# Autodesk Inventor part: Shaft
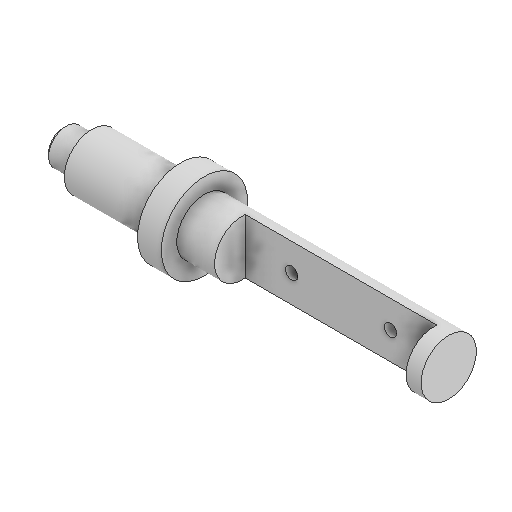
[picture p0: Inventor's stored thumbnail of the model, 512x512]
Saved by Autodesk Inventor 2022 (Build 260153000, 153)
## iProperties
Created: 2019-03
Part Number: Shaft
Material: Generic
Document SubType Name: Modeling
Designer: LENOVO-CADCIM
Density: 1 g/cm^3
Appearance: Default
Author: LENOVO-CADCIM
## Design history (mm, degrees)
sketch "Sketch1"
  geometry: L1 (284.311, 0)-(1023.188, 0); L2 (391.676, 0)-(391.676, -18); L3 (391.676, -18)-(420.576, -18); L4 (420.576, -18)-(420.576, -28); L5 (420.576, -28)-(510.376, -28); L6 (510.376, -28)-(510.376, -43.6); L7 (510.376, -43.6)-(534.376, -43.6); L8 (534.376, -43.6)-(534.376, -28); L9 (534.376, -28)-(781.476, -28); L10 (781.476, -28)-(781.476, 0); L11 (391.676, 0)-(781.476, 0); 1 further point
  constraints: 22 end point, 8 perpendicular, 5 point on line, 1 collinear, 1 horizontal
  dimensions: "d0" = 28.9 distance of L2.end L3.end; "d1" = 89.8 distance of L4.end L5.end; "d2" = 24 distance of L6.end L7.end; "d3" = 247.1 distance of L8.end L9.end; "d4" = 56 diameter of L9 L1; "d5" = 87.2 diameter of L7 L1; "d6" = 36 diameter of L3 L1
revolve "Revolution1" sketch "Sketch1" stored, may be unused: angle "d7" = 90 deg
sketch "Sketch4"
  geometry: L1 (-781.476, 28)-(-534.376, 28) reference; L2 (-572.576, 28)-(-766.376, 28); L3 (-766.376, 28)-(-766.376, -3.1); L4 (-766.376, -3.1)-(-572.576, -3.1); L5 (-572.576, -3.1)-(-572.576, 28); L6 (-781.476, -28)-(-534.376, -28) reference; 2 further points
  constraints: 8 end point, 2 parallel, 1 horizontal, 1 perpendicular, 1 point on line
  dimensions: "d16" = 24.9 distance between parallel lines of L6 L4; "d17" = 15.1 distance from line of L1.start L3; "d40" = 193.8 distance of L3.end L4.end
extrude "Extrusion3" cut sketch "Sketch4" stored distance "d18" = 257; taper "d19" = 0 deg
sketch "Sketch6"
  geometry: L1 (-180.9, 45.828)-(-180.9, 9.828) reference; L2 (-180.9, 27.828)-(320.546, 27.828); L3 (0, 55.828)-(0, -0.172) reference; 5 further points
  constraints: 2 end point, 2 point on line, 1 horizontal, 1 midpoint
  dimensions: "d24" = 100 distance of point (46.9, 27.828) point (146.9, 27.828); "d25" = 46.9 distance from line of L3 point (46.9, 27.828)
hole "Hole1" sketch "Sketch6" at (46.9, 27.828), (146.9, 27.828) diameter "d26" = 12.5; stored, may be unused: countersink angle "d30" = 90 deg, drill point angle "d32" = 118 deg; dims "d27" = 6, "d28" = 100, "d29" = 25, "d31" = 310
chamfer "Chamfer1" distance "d33" = 3; stored, may be unused: second distance "d34" = 2, angle "d35" = 45 deg
sketch "Sketch7"
  geometry: L1 (8, -22)-(-8, -22); L2 (-8, -22)-(-8, -26.833); L3 (8, -26.833)-(8, -22); L4 (0, 0)-(0, 64); C1 r 28 at (0, 0) reference; A1 r 28 centre (0, 0) between (-8, -26.833) and (8, -26.833); A2 r 28 centre (0, 0) between (8, -26.833) and (-8, -26.833) reference; 4 further points
  constraints: 8 end point, 3 point on circle, 1 centre point, 1 coincident, 1 concentric, 1 horizontal, 1 parallel, 1 perpendicular, 1 vertical, 1 other
  dimensions: "d36" = 16 distance between parallel lines of L3 L2; "d37" = 50 distance from line of point (0, 28) L1
extrude "Extrusion5" cut sketch "Sketch7" distance "d38" = 62.5; taper "d39" = 0 deg
body "Solid1"
